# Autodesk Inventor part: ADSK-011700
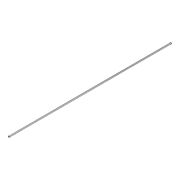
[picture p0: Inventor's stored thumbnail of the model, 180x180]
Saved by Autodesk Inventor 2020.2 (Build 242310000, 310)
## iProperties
Created: 2000-03
Part Number: ADSK-011700
Material: Pearson DGP
Document SubType Name: Modeling
Designer: sspink
Density: 7.83 g/cm^3
Appearance: Chrom - poliert
Mass: 5403.67 g
Surface Area: 1391.49 cm^2
Volume: 690.124 cm^3
Control State: 0
Master: False
Checked Out: False
Shininess: 60.0
Length Units: 11269
Angle Units: 11279
Time Units: 11290
Mass Units: 11283
Length Display Precision: 3
Angle Display Precision: 2
Compacted: True
Cutlength: 86.56
Material Desc: ROUND,DGP 1144,0.7500 DIA
Material_Number: A086420
Dimensions: 20x2200x20 mm
Mass: 5,404 kg
VLT_Material: Pearson DGP
Density: 7.83
Volumn: 625.2277487788634
Area: 1327.4670397843556
PropertySet Name: Model Information
Author: sspink
Revision Number: -
Title: ADSK-011700
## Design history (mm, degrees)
node "Chamfer1" dims "d17" = 1, "d18" = 1, "d21" = 45 deg
node "Solide1"
  node "Extrusion1" dims "d1" = 2200, "d2" = 0
sketch "Sketch1"
  geometry: C1 r 10 at (0, 0); 1 further point
  constraints: 1 centre point, 1 coincident
  dimensions: "d0" = 20 diameter of C1
workplane "Work Plane1"
workplane "Work Plane2"
sketch "Skizze6"
  geometry: L1 (0, -876)-(0, -845); L2 (2.5, -876)-(2.5, -845); L3 (-2.5, -845)-(-2.5, -876); L4 (9, -1100)-(-9, -1100) reference; L5 (0, 1000)-(0, 1031); L6 (2.5, 1000)-(2.5, 1031); L7 (-2.5, 1031)-(-2.5, 1000); L8 (2.5, -1100)-(2.5, -1070); L9 (-2.5, -1070)-(-2.5, -1100); L10 (-2.5, -1100)-(2.5, -1100); A1 r 2.5 centre (0, -876) between (-2.5, -876) and (2.5, -876); A2 r 2.5 centre (0, -845) between (2.5, -845) and (-2.5, -845); A3 r 2.5 centre (0, 1000) between (-2.5, 1000) and (2.5, 1000); A4 r 2.5 centre (0, 1031) between (2.5, 1031) and (-2.5, 1031); A5 r 2.5 centre (0, -1070) between (2.5, -1070) and (-2.5, -1070); 4 further points
  constraints: 22 end point, 10 point on circle, 10 tangent, 5 centre point, 4 vertical alignment, 3 midpoint, 3 vertical, 2 parallel, 2 point on line, 1 collinear, 1 perpendicular
  dimensions: "d22" = 31 distance of L1.start L1.end; "d23" = 5 diameter of A2; "d24" = 5 diameter of A4; "d25" = 31 distance of L5.start L5.end; "d26" = 224 distance from line of L4 L1.start; "d27" = 2100 distance from line of L5.start L4; "d28" = 5 distance of L9.end L8.start; "d29" = 30 distance of L9.start L9.end
extrude "Extrusion5" cut sketch "Skizze6" distance "d30" = 2; taper "d31" = 0 deg
workplane "Arbeitsebene3"
node "Corps solides"
node "Corps surfaciques"
other parameters: "d3" = -215.9, "d4" = -2082.8
